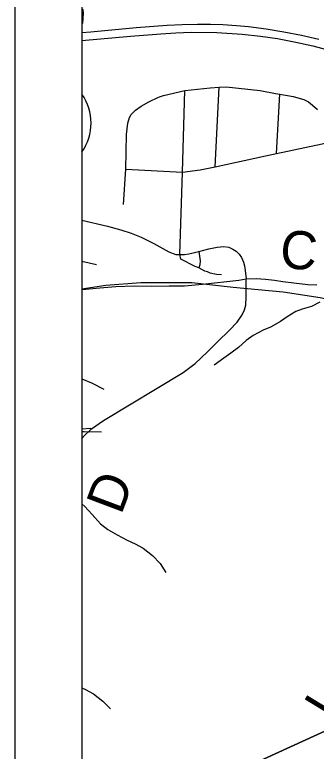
# Model space of a CAD drawing. Extents: x 0 to 34, y 0 to 22.
# Drawn here: x 2 to 2.449, y 16.134 to 17.231 of the extents above; entities that cross this region are included whole.
import ezdxf

# ---------------------------------------------------------------- set-up
doc = ezdxf.new("R2010")
doc.units = 0
for name, color, linetype in [('GM_X_Corporation', 7, 'Continuous'), ('GM_X_County_Road', 7, 'Continuous'), ('GM_X_County_Road_Text', 7, 'Continuous'), ('GM_X_Minor_River', 7, 'Continuous'), ('GM_X_Rail_Line', 7, 'Continuous'), ('GM_X_State_Shield', 7, 'Continuous'), ('GM_X_Township_Road', 7, 'Continuous'), ('GM_X_Township_Road_Text', 7, 'Continuous'), ('GM_X_US_Route', 7, 'Continuous'), ('SH_Data', 7, 'Continuous')]:
    doc.layers.add(name, color=color, linetype=linetype)

msp = doc.modelspace()

# ---------------------------------------------------------------- linework, layer by layer
at = {"layer": 'GM_X_Corporation'}
msp.add_line((2.1, 20.9), (2.1, 15.8164), dxfattribs=at)
for points in [[(2.1, 20.9), (2.1, 15.9991), (2.5081, 16.1858), (2.5106, 16.1869), (3.1538, 16.4811), (3.1598, 16.4838), (3.1648, 16.4862), (3.1819, 16.4943), (3.1836, 16.4951), (3.3801, 16.588), (3.8146, 16.7867), (3.8864, 16.8187), (4.2007, 16.9645), (4.2041, 17.0039), (4.5514, 17.1703), (4.4931, 17.1874), (4.4442, 17.208), (4.4091, 17.232)], [(3.3801, 16.588), (3.1836, 16.4951), (3.1819, 16.4943), (3.1648, 16.4862), (3.1598, 16.4838), (3.1538, 16.4811), (2.5106, 16.1869), (2.5081, 16.1858), (2.1, 15.9991), (2.1, 14.1), (7.2283, 14.1)]]:
    msp.add_lwpolyline(points, dxfattribs=at)
at = {"layer": 'GM_X_County_Road'}
for p, q in [((2.1, 16.6886), (2.1143, 16.6827)), ((2.1143, 16.6827), (2.1328, 16.6735)), ((2.1, 16.6103), (2.1035, 16.6105)), ((2.1035, 16.6105), (2.129, 16.6099))]:
    msp.add_line(p, q, dxfattribs=at)
for points in [[(2.1, 16.9251), (2.1379, 16.9162), (2.158, 16.9105), (2.1733, 16.9055), (2.1884, 16.8994), (2.2069, 16.8901), (2.2295, 16.8776), (2.24, 16.874), (2.246, 16.8736), (2.2529, 16.8739), (2.2591, 16.8748), (2.2742, 16.8784), (2.289, 16.8821), (2.3012, 16.8848), (2.3115, 16.8857), (2.3187, 16.8846), (2.3248, 16.8819), (2.3296, 16.8786), (2.3339, 16.8745), (2.3375, 16.8691), (2.3404, 16.8624), (2.342, 16.857), (2.3432, 16.8502), (2.3447, 16.8377), (2.3592, 16.838), (2.3734, 16.8369), (2.3865, 16.8354), (2.3992, 16.8338), (2.4155, 16.8318), (2.4362, 16.8293), (2.4495, 16.8285)], [(2.1, 16.8215), (2.1058, 16.8224), (2.1266, 16.8242), (2.1503, 16.8262), (2.1776, 16.8271), (2.2031, 16.8265), (2.2298, 16.8271), (2.2529, 16.8274), (2.2793, 16.8295), (2.3337, 16.8354), (2.3447, 16.8377)]]:
    msp.add_lwpolyline(points, dxfattribs=at)
at = {"layer": 'GM_X_Minor_River'}
for p, q in [((2.1, 16.2289), (2.1054, 16.2264)), ((2.1054, 16.2264), (2.1171, 16.2199)), ((2.1171, 16.2199), (2.131, 16.2091)), ((2.131, 16.2091), (2.1426, 16.1973))]:
    msp.add_line(p, q, dxfattribs=at)
for points in [[(2.454, 16.8029), (2.4415, 16.7962), (2.4278, 16.7922), (2.4183, 16.7892), (2.4053, 16.781), (2.3958, 16.7743), (2.3809, 16.7657), (2.3699, 16.7612), (2.3551, 16.7534), (2.3444, 16.7459), (2.3329, 16.7354), (2.3218, 16.7268), (2.3115, 16.7196), (2.297, 16.7091)], [(2.1, 16.5025), (2.1043, 16.4988), (2.1152, 16.4869), (2.1275, 16.4728), (2.1388, 16.4647), (2.1527, 16.4566), (2.1674, 16.4485), (2.1795, 16.4431), (2.1911, 16.4365), (2.205, 16.4258), (2.2167, 16.4139), (2.2248, 16.4002)]]:
    msp.add_lwpolyline(points, dxfattribs=at)
at = {"layer": 'GM_X_Rail_Line'}
msp.add_line((2.1, 16.6144), (2.1134, 16.6154), dxfattribs=at)
msp.add_lwpolyline([(2.1, 16.8228), (2.1358, 16.8282), (2.1875, 16.8321), (2.2635, 16.8323), (2.3249, 16.8251), (2.3996, 16.8184), (2.4546, 16.8097), (2.5216, 16.7954), (2.5976, 16.772), (2.6544, 16.7517), (2.7256, 16.7157), (2.7928, 16.6809), (2.8517, 16.6435), (2.9129, 16.5996), (3.0775, 16.4694), (3.2031, 16.3691), (3.3322, 16.2662), (3.4651, 16.1627), (3.5695, 16.0783), (3.7315, 15.9489), (3.9997, 15.7391), (4.1856, 15.5884)], dxfattribs=at)
at = {"layer": 'GM_X_State_Shield'}
msp.add_line((2.1, 17.1124), (2.1, 17.0264), dxfattribs=at)
msp.add_arc((2.0393, 17.0694), 0.0744, 324.7112, 35.2888, dxfattribs=at)
at = {"layer": 'GM_X_Township_Road'}
for p, q in [((2.2982, 17.0045), (2.3044, 17.1227)), ((2.3897, 17.024), (2.3944, 17.1124)), ((2.1617, 16.9483), (2.1654, 17.0008)), ((2.1, 16.8638), (2.1218, 16.8591))]:
    msp.add_line(p, q, dxfattribs=at)
for points in [[(2.1012, 17.2177), (2.1021, 17.2254), (2.1024, 17.2325), (2.1017, 17.2379), (2.1, 17.2402)], [(2.1654, 17.0008), (2.1663, 17.0524), (2.1683, 17.0695), (2.1708, 17.0777), (2.1735, 17.0821), (2.1798, 17.0886), (2.1884, 17.0948), (2.1995, 17.1011), (2.214, 17.1079), (2.2215, 17.1103), (2.2532, 17.118), (2.2908, 17.1219), (2.3044, 17.1227), (2.3147, 17.1232), (2.3655, 17.1178), (2.388, 17.1135), (2.3944, 17.1124), (2.4146, 17.1089), (2.4301, 17.1043), (2.4372, 17.1009), (2.4433, 17.0963), (2.4505, 17.0899)], [(2.246, 16.8736), (2.2496, 16.9966), (2.2532, 17.118)], [(2.1654, 17.0008), (2.2496, 16.9966), (2.276, 16.9998), (2.2982, 17.0045), (2.3732, 17.0205), (2.3897, 17.024), (2.4577, 17.0384), (2.4687, 17.041)], [(2.2742, 16.8784), (2.276, 16.8645), (2.2757, 16.8582), (2.2739, 16.8539), (2.2686, 16.8557), (2.2474, 16.867), (2.246, 16.8736)], [(2.3078, 16.8434), (2.3004, 16.8442), (2.2908, 16.8462), (2.287, 16.8478), (2.2832, 16.8492), (2.2739, 16.8539)], [(2.1, 16.5995), (2.102, 16.6024), (2.1144, 16.6143), (2.1321, 16.6267), (2.2508, 16.698), (2.2687, 16.7114), (2.287, 16.7288), (2.3024, 16.7444), (2.3191, 16.7609), (2.3309, 16.7729), (2.3386, 16.7838), (2.342, 16.7914), (2.3438, 16.7985), (2.3447, 16.8108), (2.3447, 16.8377)]]:
    msp.add_lwpolyline(points, dxfattribs=at)
at = {"layer": 'GM_X_US_Route'}
for points in [[(2.1, 17.2042), (2.1133, 17.2054), (2.1808, 17.2116), (2.2267, 17.2153), (2.2493, 17.2164), (2.2722, 17.2168), (2.2914, 17.2167), (2.31, 17.2161), (2.3299, 17.2147), (2.3481, 17.213), (2.3745, 17.2098), (2.4006, 17.2055), (2.4268, 17.2005), (2.4526, 17.1943)], [(2.1, 17.1922), (2.1721, 17.1987), (2.2176, 17.2025), (2.2398, 17.2039), (2.2626, 17.2046), (2.3008, 17.2043), (2.3383, 17.202), (2.3656, 17.1988), (2.3911, 17.1951), (2.4186, 17.19), (2.4435, 17.1842), (2.4697, 17.1774)]]:
    msp.add_lwpolyline(points, dxfattribs=at)
at = {"layer": 'SH_Data'}
for p, q in [((2, 21), (2, 14)), ((2.1, 20.9), (2.1, 14.1))]:
    msp.add_line(p, q, dxfattribs=at)

# ---------------------------------------------------------------- texts
at = {"layer": 'GM_X_County_Road_Text'}
msp.add_text('C', height=0.0568, rotation=354.5391, dxfattribs=at).set_placement((2.393, 16.8547))
at = {"layer": 'GM_X_Township_Road_Text'}
for s, rotation, p in [('D', 69.372, (2.1583, 16.4849)), ('L', 58.5688, (2.4769, 16.1767))]:
    msp.add_text(s, height=0.0568, rotation=rotation, dxfattribs=at).set_placement(p)

doc.saveas('drawing.dxf')
